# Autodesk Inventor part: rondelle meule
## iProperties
Shininess: 64.0
Length Units: 11269
Angle Units: 11279
Time Units: 11290
Mass Units: 11283
Length Display Precision: 3
Angle Display Precision: 2
Compacted: True
Part Number: rondelle meule
Document SubType Name: Modeling
Created: 2005-01
Material: Par défaut
Designer: LEGERET Philippe
Density: 0.0
Volumn: 0.0
Area: 0.0
PropertySet Name: Model Information
Control State: 0
Master: False
Checked Out: False
Author: LEGERET Philippe
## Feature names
1. Extrusion1
2. Extrusion2
3. Chanfrein1 [Chamfer]
4. Perçage1 [Hole]
